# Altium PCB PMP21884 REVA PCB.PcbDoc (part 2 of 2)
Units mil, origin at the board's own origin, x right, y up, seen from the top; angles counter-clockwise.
Board outline 2378 x 1724 mil, 4 copper layers (Top Layer, Signal Layer 1, Signal Layer 2, Bottom Layer), stack 61.6 mil thick; 76 components, 35 nets, 187 pads, 142 vias.
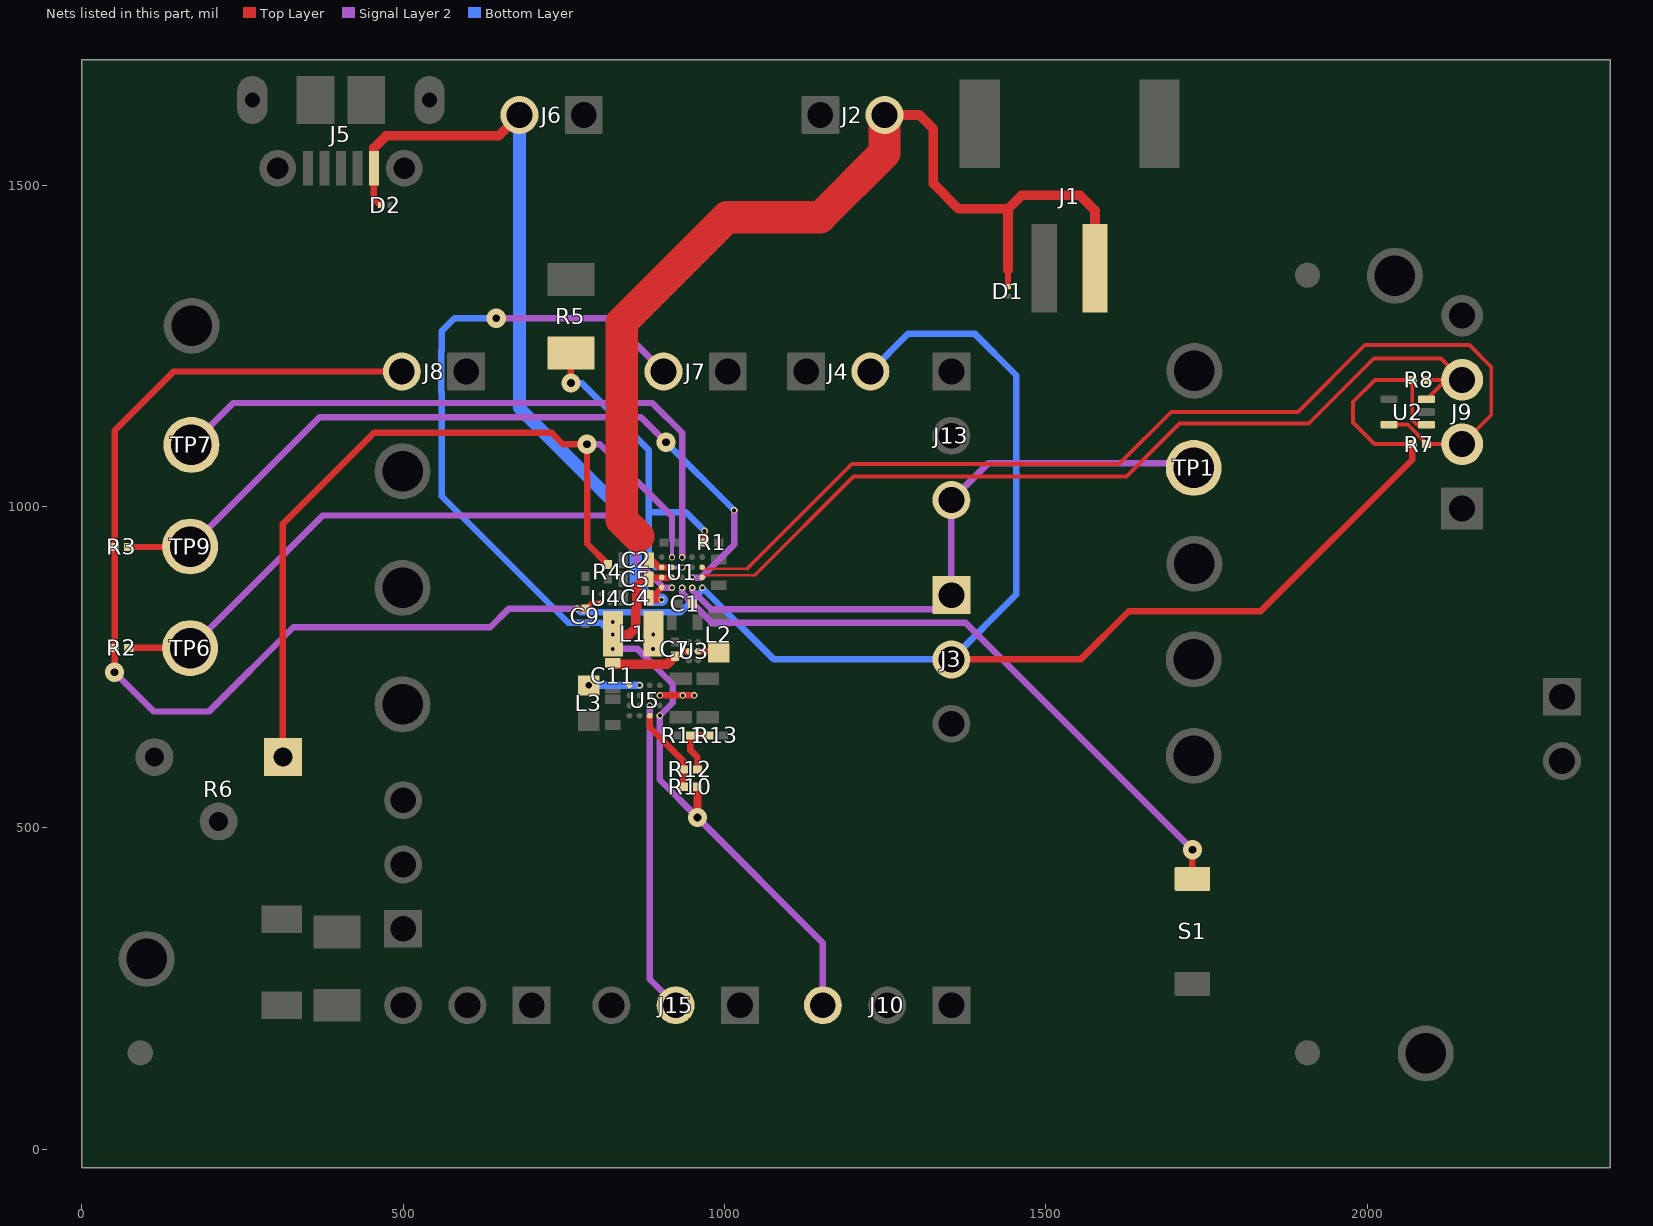
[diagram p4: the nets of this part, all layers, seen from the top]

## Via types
v1: diameter 30, hole 12, Top Layer to Bottom Layer, tented both sides, 95 vias
v2: diameter 10, hole 6, Top Layer to Bottom Layer, tented bottom, 30 vias
v3: diameter 10, hole 6, Top Layer to Bottom Layer, tented both sides, 16 vias
v4: diameter 20, hole 10, Top Layer to Bottom Layer, tented bottom, 1 vias

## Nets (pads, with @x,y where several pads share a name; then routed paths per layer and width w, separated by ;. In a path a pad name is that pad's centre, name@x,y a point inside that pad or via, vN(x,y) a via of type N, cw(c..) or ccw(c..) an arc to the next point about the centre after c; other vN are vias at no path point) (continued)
NetJ15_2: J15.2 U5.B3 | length 483
  Signal Layer 2 w10: v2(883.62,690.29) 883.62,264.38 J15.2@924,224
NetL1_2: L1.2 U5.A2 | length 53.6
  Top Layer w10: v2(899.37,706.04) v3(953,706) v3(953,706)
  other v2: 889,778 889.12,800.61
  other v3: 935,706.04
NetL2_1: L2.1 U3.B2 | length 32.8
  Top Layer w10: U3.B2@958.72,774.78 988.82,774.78 L2.1@990.72,772.89
NetL3_1: L3.1 U5.C1 | length 79
  Bottom Layer w12: v4(789,721.56) 789.23,721.78 v2(867.87,721.78)
NetR1_1: R1.1 R5.2 U1.C3 | length 556
  Top Layer w10: v1(761,1192) R5.2@761,1238.91 ; R1.1@968.95,944 R1.1@968.95,944 v3(969,962)
  Bottom Layer w6: 893.52,905.1 v2(934,905.1)
  Bottom Layer w10: v1(761,1192) 778,1192 882.21,1087.79 882.21,991 ; 893.52,905.1 882.21,916.41 882.21,991 ; v3(969,962) 940,991 882.21,991
NetR2_2: R2.2 TP6.1 U1.B1 | length 995.1
  Top Layer w10: R2.2@73.05,780 168.32,780 TP6.1@168.6,779.72
  Signal Layer 2 w10: TP6.1@168.6,779.72 374.88,986 823.2,986 862.82,946.38 862.82,916 905.22,873.61 v2(918.25,873.61)
NetR3_2: R3.2 TP9.1 U1.D2 | length 1225.3
  Top Layer w10: R3.2@73.05,937 167.88,937 TP9.1@168.6,937.72
  Signal Layer 2 w10: TP9.1@168.6,937.72 369.84,1138.96 870.04,1138.96 v1(909,1100) ; v2(949.75,889.36) 963.36,889.36 1015,941 v3(1015,994)
  Bottom Layer w10: v1(909,1100) v3(1015,994)
NetR4_1: R4.1 R6.1 U1.B4 | length 1345.9
  Top Layer w10: R6.1@313,610 313,973 455,1115 730.42,1115 748.42,1097 v1(786,1097) 786,1044 786.24,1044 786.24,942.04 R4.1@818.62,909.66
  Signal Layer 2 w6: v2(918.25,920.85) 918.25,948
  Signal Layer 2 w10: v1(786,1097) 806,1097 918.25,984.75 918.25,948
NetR10_1: R10.1 R12.2 U5.B4 | length 132.2
  Top Layer w10: U5.B4@883.62,674.54 883.62,656.38 935.95,604.05 R12.2@935.95,591 R10.1@935.95,564
NetR11_1: R11.1 R12.1 R13.2 | length 87
  Top Layer w10: R12.1@957.64,591.36 R12.1@958,591 958,610 947,621 R11.1@947,644 R13.2@975.98,644
NetS1_2: S1.2 U1.C1 | length 1012.9
  Top Layer w10: S1.2@1728,420.69 v1(1728,466)
  Signal Layer 2 w10: v2(934,873.61) 934,865.51 980.51,819 1375,819 v1(1728,466)
NetTP7_1: TP7.1 U1.C4 | length 1003.5
  Signal Layer 2 w10: TP7.1@170.6,1095.72 235.88,1161 887.75,1161 934,1114.75 v2(934,920.85)
PMID: C5.1 C7.1 C11.1 J7.2 J10.3 L1.1 R10.2 U1.A2 U1.B2 U3.B1 U5.A4 U5.D1 | length 2067.8
  Top Layer w10: C5.1@882.21,886.76 884.81,889.36 U1.B2@918.25,889.36 ; C7.1@923,766.98 927.07,766.98 934.87,774.78 U3.B1@944.94,774.78
  Top Layer w12: v1(958,516) R10.2@958,564
  Top Layer w15: C11.1@825.99,756.92 828.41,754.5 910.52,754.5 C7.1@923,766.98 ; v2(826.12,800.61) 851.42,800.61 861.87,811.05 861.87,838.83 ; 862.7,842.65 863.21,843.16 ; 863.21,842.15 863.21,843.16 ; C5.1@882.21,886.76 875.45,886.76 863.21,874.52 863.21,843.16
  Signal Layer 2 w10: v1(645,1293) 822,1293 J7.2@905,1210 ; v2(826.12,778.36) 864.64,778.36 919.37,723.63 919.37,694.54 v2(899.37,674.54) 899.37,574.63 v1(958,516) 1153,321 J10.3@1153,224
  Bottom Layer w10: v1(645,1293) 580,1293 560,1273 560,1242.57 559.47,1242.04 559.47,1177.96 560,1177.43 560,1016 757,819 807.73,819 v2(826.12,800.61)
  other v2: 826.12,820.36
SCL: J9.2 R7.1 U1.E3 U2.5 | length 1653.5
  Top Layer w4: U1.E3@965.5,903.11 1035.11,903.11
  Top Layer w6: U1.E3@965.5,903.11 U1.E3@965.5,905.1 ; 1035.11,903.11 1198,1066 1614,1066 1695,1147 1892,1147 1996,1251 2159,1251 2193,1217 2193,1142.41 J9.2@2147.59,1097 R7.1@2092,1097 2092,1098.24 2062.92,1127.31 U2.5@2033.84,1127.31
SDA: J9.3 R8.2 U1.E2 U2.3 | length 1435.3
  Top Layer w4: U1.E2@965.5,889.36 969.25,893.11 1047.11,893.11
  Top Layer w6: 1047.11,893.11 1200.53,1046.53 1625.53,1046.53 1708,1129 1909,1129 2010,1230 2114.59,1230 J9.3@2147.59,1197 J9.3@2122.43,1197 ; R8.2@2092,1197 J9.3@2122.43,1197 ; U2.3@2092.11,1166.68 J9.3@2122.43,1197
VBAT: C2.1 D1.2 J1.1 J2.2 U1.A3 U1.B3 | length 1627.7
  Top Layer w10: C2.1@882.43,916.19 887.37,916.19 898.45,905.1 U1.B3@918.25,905.1 ; D1.2@1441,1342.16 1441,1368
  Top Layer w15: J2.2@1249,1609 1303,1609 1325,1587 1325,1502.25 1364.25,1463 1441,1463 ; 1441,1368 1441,1463 ; J1.1@1576.37,1370.86 1576.37,1460.63 1553,1484 1462,1484 1441,1463
  Top Layer w50: 866,953.14 840.2,978.93 840.2,1286.22 1003.98,1450 1149,1450 1249,1550 J2.2@1249,1609
VDD: C1.1 J3.1 J13.3 TP1.1 U1.D1 | length 980.2
  Signal Layer 2 w10: v2(949.75,873.61) 949.75,869.56 979.31,840 1331,840 J3.1@1353,862 J13.3@1353,1010 1410,1067 1723,1067 TP1.1@1730,1060
VIN: C4.1 D2.2 J5.1 J6.2 U1.A1 | length 1239.7
  Top Layer w10: J5.1@454.39,1526.3 454.39,1479.04 D2.2@464.42,1469 ; C4.1@882.21,857.76 C4.1@886.66,857.76 ; v3(902,855) 889.42,855 C4.1@886.66,857.76 ; U1.A1@902.51,873.61 C4.1@886.66,857.76
  Top Layer w15: J5.1@454.39,1526.3 454.39,1557.98 473,1576.6 648.6,1576.6 J6.2@681,1609
  Bottom Layer w20: J6.2@681,1609 681,1152.75 861.87,971.88 861.87,878.1 884.97,855 v3(902,855)
VIO: C9.1 J3.2 J4.2 J8.2 R2.1 R3.1 R7.2 R8.1 U1.E1 U2.1 U4.A1 | length 4326.5
  Top Layer w6: R7.2@2069.95,1097 2011.41,1097 1978,1130.41 1978,1163 2012,1197 R8.1@2069.95,1197 2069.95,1134.43 2077.07,1127.31 U2.1@2092.11,1127.31
  Top Layer w8: C9.1@783.62,840.28 783.95,840.61 793.45,850.11 U4.A1@808.11,850.11
  Top Layer w10: v1(51,742) R2.1@51,780 R3.1@51,937 51,1118 143,1210 J8.2@498,1210 ; v3(771,840.61) C9.1@783.95,840.61 ; J3.2@1353,762 1553.82,762 1628.82,837 1834,837 2069.95,1072.95 R7.2@2069.95,1097
  Signal Layer 2 w10: v1(51,742) 112,681 198,681 329,812 635.39,812 664,840.61 v3(771,840.61)
  Bottom Layer w10: v3(771,840.61) 776,835.61 931.55,835.61 965.5,869.56 v2(965.5,873.61) 1077.11,762 J3.2@1353,762 1454,863 1454,1204 1389,1269 1286,1269 J4.2@1227,1210
pads on no net: FID1.1 FID2.1 FID3.1 J1.M1 J1.M2 J5.2 J5.3 J5.4 J9.4 U2.2

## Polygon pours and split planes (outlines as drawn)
1V2 on Top Layer "TOP_LAYER_1V2_P012" (solid, remove dead copper, pour order 12): 813,859 768,859 768,880 801,880 813.01,867.99
VDD on Top Layer "TOP_LAYER_VDD_P058" (solid, remove dead copper, pour order 58): 950,876.61 942,868.61 942,837.61 943,836.61 956,836.61 956,870.61
GND on Top Layer "TOP_LAYER_GND_P028" (solid, remove dead copper, pour order 28): 0,-29 2378,-29 2378,1695 0,1695
GND on Signal Layer 2 "SIGNAL_LAYER_2_GND_P030" (solid, remove dead copper, pour order 30): 0,-29 2378,-29 2378,1695 0,1695
GND on Signal Layer 1 "SIGNAL_LAYER_1_GND_P032" (solid, remove dead copper, pour order 32): 0,-29 2378,-29 2378,1695 0,1695
GND on Bottom Layer "BOTTOM_LAYER_GND_P034" (solid, remove dead copper, pour order 34): 0,-29 2378,-29 2378,1710 0,1710

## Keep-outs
Keep-Out Layer:
  text ".Layer_Name" at 537,-918.49 h60

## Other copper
Top Layer:
  region: 945,780
  region net PMID: 810.62,835.61 810.62,791.61 852.61,791.61 869.62,808.62 869.62,842.61 854.62,842.61 847.62,835.61
  region net PMID: 848,806 856,798 856,719 852,719 840,731 814.42,731 810.42,735 810.42,806
  region net 1V8_C: 855,694 846,694 834,682 772,682 772,651 774,649 838,649 840,651 840,676 855,691
  region net GND: 814,724 814,692 838,692 838,695 844,701 854,701 857,704 857,709 855,711 848,711 835,724
  region net VIN: 906,877 899,877 892,870 875,870 875,846 906,846 911,851 911,859 905.97,864.03
  region net 12V: 915,663 915,678 908,685 898,685 898,695 923,695 923,663
  region net 1V8_B: 958.32,784.31 958.32,803.04 952.19,809.18 952.19,829.19 976.18,853.18 1041.19,853.18 1053.19,841.18 1053.19,816.04 1040.19,803.04 977.06,803.04
  region net VBAT: 906,901 906,904 900,910 891.75,910 890,911.75 890,957 880,967 830,967 857,940 857,911 865,903 892,903 894,901
  region net GND: 944.94,785.41
  text ".Layer_Name" at 537,-918.49 h60
Signal Layer 2:
  region: 863.75,858.7
Bottom Layer:
  region net NetL1_2: 898,711 904,711 911,718 911,731 875,767 875,807 904,807 904,789 963,730 963,698 905,698 898,705
  text ".Layer_Name" at 537,-918.49 h60

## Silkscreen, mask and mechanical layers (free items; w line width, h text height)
Top Overlay:
  region: 1003.6,955.81
  region: 910.44,833.78
  lines w10: 249,926 324,926 ; 255,769 305,769 ; 574,1323 624,1323 ; 1103,1319 1153,1319 ; 1798,396 1848,396
  text "'.PRJ_Number'.PCB_Rev" at 1756,1549 h108.27
  text "VIN" at 632,1508 h30
  text "GND" at 751,1508 h30
  text "GND" at 1094,1508 h30
  text "VBAT" at 1205,1508 h30
  text "GND" at 2126,1355 h30
  text "GND" at 252,1284 h30
  text "VIO" at 458,1279 h30
  text "CE" at 574,1279 h30
  text "PMID" at 820,1277 h30
  text "VINLS" at 944,1277 h30
  text "LP" at 1105,1277 h30
  text "VIO" at 1201,1277 h30
  text "OFF" at 1416,1198 h30
  text "1V8_A" at 1812,1171 h30
  text "1V8_B" at 1416,1100 h30
  text "ADCIN" at 252,1062 h30
  text "1V2" at 583,1026 h30
  text "VDD" at 1812,1007 h30
  text "ON" at 1416,994 h30
  text "INT" at 250,883 h30
  text "1V8_B" at 1812,876 h30
  text "1V8_C" at 578,849 h30
  text "VDD" at 1416,836 h30
  text "VIO" at 1416,734 h30
  text "PG" at 255,728 h30
  text "12V" at 1812,718.84 h30
  text "GND" at 2145.96,682 h30
  text "1V8_D" at 579,659 h30
  text "EXT_VIO" at 1416,639 h30
  text "EXT_VIO" at 2031,583 h30
  text "GND" at 1809,560 h30
  text "ON" at 565,532 h30
  text "1V2" at 565,434 h30
  text "MR" at 1799,353 h30
  text "OFF" at 565,329 h30
  text "GND" at 180,303 h30
  text "GND" at 2174,146 h30
  text "ON" at 517,105.99 h30 r90
  text "ON" at 840,105.99 h30 r90
  text "ON" at 1169,105.99 h30 r90
  text "12V" at 938,81 h30 r90
  text "OFF" at 720,76 h30 r90
  text "OFF" at 1043,76 h30 r90
  text "OFF" at 1372,76 h30 r90
  text "1V8_C" at 615,21.02 h30 r90
  text "1V8_D" at 1267,21.02 h30 r90
  text ".Layer_Name" at 537,-918.49 h60
Bottom Overlay:
  text ".Layer_Name" at 537,-918.49 h60
Top Paste:
  text ".Layer_Name" at 537,-918.49 h60
Bottom Paste:
  text ".Layer_Name" at 537,-918.49 h60
Top Solder:
  text ".Layer_Name" at 537,-918.49 h60
  text ".Layer_Name" at 537,-918.49 h60
Bottom Solder:
  text ".Layer_Name" at 537,-918.49 h60
Drill Guide:
  text ".Layer_Name" at 537,-918.49 h60
M1 Board Outline:
  the board outline again, w10
  text ".Layer_Name" at 537,-918.49 h60
M2 Board Dimensions:
  rectangle: -40,-335 85,-210
  rectangle: 85,-460 460,-335
  lines w7: -40,-335 960,-335 ; 85,-460 85,-210 ; 210,-460 210,-210 ; 460,-460 460,-210 ; 710,-460 710,-210 ; -40,-460 960,-460 960,-210 -40,-210 -40,-460
  text ".Layer_Name" at 537,-918.49 h60
M3 3D STEP Top:
  text ".Layer_Name" at 537,-918.49 h60
M4 3D STEP Bottom:
  text ".Layer_Name" at 537,-918.49 h60
M5 Assembly Top:
  lines w10: -332,-990.17 6268,-990.17 ; -332,-786.83 6270,-786.83 ; -332,-583.5 -332,-1193.5 3673,-1193.5 6270,-1193.5 6270,-583.5 -331.5,-583.5 -331.5,-1193.5 1244,-1193.5 ; 2133,-1193.5 2133,-583.5 ; 3400,-786.83 3400,-583.5 ; 4240,-786.83 4240,-583.5 ; 4862,-1200 4862,-997.17
  text "COMPONENTS MARKED 'DNP' SHOULD NOT BE POPULATED." at 1113.5,-378.5 h60
  text "ASSEMBLY VARIANT:" at 1113,-494 h60
  text ".VariantName" at 2149,-494 h60
  text "PCB VIEWED FROM TOP SIDE" at -268.5,-715.67 h60
  text "BOARD #:" at 2208,-715.67 h60
  text ".PRJ_Number" at 2753.5,-715.67 h60
  text "REV:" at 3598,-715.67 h60
  text ".PCB_Rev" at 3889.5,-715.67 h60
  text "SVN REV:" at 4436,-715.67 h60
  text ".VersionControl_RevNumber" at 4942,-715.67 h60
  text "TID #:" at 2208,-919 h60
  text ".TID" at 2753.5,-919 h60
  text "PLOT NAME =" at -268.5,-1124.34 h60
  text ".plot_File_Name" at 537,-1124.34 h60
  text "GENERATED    :" at 2210,-1124.34 h60
  text ".Print_Date" at 3079.5,-1124.34 h60
  text ".Print_Time" at 3808.5,-1124.34 h60
  text "TEXAS INSTRUMENTS" at 5073,-1124.34 h60
M6 Assembly Bottom:
  lines w10: -332.5,-787.33 6269.5,-787.33 ; -330.5,-990.67 6269.5,-990.67 ; 1075.5,-1200.5 1075.5,-997.67 ; 1697.5,-787.33 1697.5,-584 ; 2537.5,-787.33 2537.5,-584 ; 3804.5,-1194 3804.5,-584 ; 4693.5,-1194 6269,-1194 6269,-584 -332.5,-584 -332.5,-1194 2264.5,-1194 6269.5,-1194 6269.5,-584
  text "COMPONENTS MARKED 'DNP' SHOULD NOT BE POPULATED." at 6062,-378 h60
  text ".VariantName" at 5018,-494 h60
  text "ASSEMBLY VARIANT:" at 6057,-494 h60
  text ".VersionControl_RevNumber" at 995.5,-716.17 h60
  text "SVN REV:" at 1501.5,-716.17 h60
  text ".PCB_Rev" at 2048,-716.17 h60
  text "REV:" at 2339.5,-716.17 h60
  text ".PRJ_Number" at 3184,-716.17 h60
  text "BOARD #:" at 3729.5,-716.17 h60
  text "PCB VIEWED FROM BOTTOM SIDE" at 6206,-716.17 h60
  text ".TID" at 3184,-919.5 h60
  text "TID #:" at 3729.5,-919.5 h60
  text "TEXAS INSTRUMENTS" at 864.5,-1124.84 h60
  text ".Print_Time" at 2129,-1124.84 h60
  text ".Print_Date" at 2858,-1124.84 h60
  text "GENERATED    :" at 3727.5,-1124.84 h60
  text ".plot_File_Name" at 5400.5,-1124.84 h60
  text "PLOT NAME =" at 6206,-1124.84 h60
M9 Title Sheet:
  drawing of 57 lines, arcs and shapes, not listed
  text "1" at 699.84,7976.5 h70
  text "2" at 3195.5,7976.5 h70
  text "3" at 5684.84,7976.5 h70
  text "4" at 8191.51,7976.5 h70
  text "5" at 10690.5,7976.5 h70
  text "6" at 13195.5,7976.5 h70
  text "A" at -456.5,6833.5 h70
  text "A" at 14343.5,6833.5 h70
  text "B" at -456.5,4453.5 h70
  text "B" at 14343.5,4453.5 h70
  text "C" at -456.5,2078.5 h70
  text "C" at 14343.5,2078.5 h70
  text "PROJECT TITLE:" at 11303.5,217.5 h45
  text ".PRJ_Title" at 11353.5,84.17 h70
  text "DESIGNED FOR:" at 11303.5,-83.5 h45
  text ".PRJ_Customer" at 11353.5,-223.5 h70
  text "D" at -456.5,-291.5 h70
  text "D" at 14343.5,-291.5 h70
  text "FILE NAME:" at 11303.5,-383.5 h45
  text ".PCB_File_Name_No_Path" at 11353.5,-503.5 h70
  text "Texas Instruments (TI) and/or its licensors do not warrant the accuracy or completeness of this specification" at 6334,-665.34 h45
  text "ENGINEER:" at 11303.5,-673.5 h45
  text "LAYOUT BY:" at 12808.5,-673.5 h45
  text "or any information contained therein. TI and/or its licensors do not warrant that this design will meet" at 6289.01,-778 h45
  text ".PRJ_Engineer" at 11353.5,-828.49 h70
  text ".PCB_Layout" at 12859,-828.49 h70
  text "the specifications, will be suitable for your application or fit for any particular purpose, or will operate in" at 6289.01,-890.67 h45
  text ".Layer_Name" at 537,-918.49 h60
  text "ALTIUM DESIGNER VERSION:" at 12808.5,-983.5 h45
  text "an implementation. TI and/or its licensors do not warrant that the design is production worthy. You should" at 6289.01,-1003.33 h45
  text "completely validate and test your design implementation to confirm the system functionality for your application." at 6334,-1116 h45
  text ".print_Scale" at 11353.5,-1116.83 h70
  text ".Application_BuildNumber" at 12859,-1116.83 h70
  text "1" at 699.84,-1323.5 h70
  text "2" at 3195.5,-1323.5 h70
  text "3" at 5684.84,-1323.5 h70
  text "4" at 8191.51,-1323.5 h70
  text "5" at 10690.5,-1323.5 h70
  text "6" at 13195.5,-1323.5 h70
M10 Fab Notes:
  drawing of 189 lines, arcs and shapes, not listed
  text "DESIGN INFORMATION" at 12342.02,6296.17 h60
  text "MIN. TRACK WIDTH:" at 11697.46,6164.05 h60
  text "8" at 12793.7,6164.05 h60
  text "MIL" at 12948.46,6164.05 h60
  text "MIN. CLEARANCE:" at 11697.46,6039.92 h60
  text "0.2" at 12733.7,6039.93 h60
  text "mm" at 12948.46,6039.92 h60
  text "MIN. VIA PAD SIZE:" at 11697.46,5915.8 h60
  text "24" at 12763.71,5915.8 h60
  text "MIL" at 12948.46,5915.8 h60
  text "0.05mm (2MIL)" at 12392.46,5785.9 h60
  text "MINIMUM ANNULAR RING" at 11368.23,5777.67 h60
  text "EXTERNAL" at 13100.46,5777.67 h60
  text "PER" at 11568.23,5667.55 h60
  text "IPC-D-275 CLASS 2 LEVEL C" at 11788.23,5667.54 h60
  text "MIL, HOLES" at 13276.46,5567.07 h60
  text "+/-" at 12884,5558.48 h60
  text "+/-" at 13738,5558.48 h60
  text "REGISTRATION TOLERANCES:" at 11368.23,5557.42 h60
  text "METAL" at 12568,5557.42 h60
  text "5" at 13144.2,5557.42 h60
  text "3" at 13977.2,5557.42 h60
  text "MIL" at 14093.46,5557.42 h60
  text "HOLE SIZE TOLERANCE (UNLESS OTHERWISE SPECIFIED):" at 11368.23,5459.1 h60
  text "+/-" at 13738,5456.23 h60
  text "3" at 13977.2,5455.17 h60
  text "MIL" at 14093.46,5455.17 h60
  text "MATERIAL:" at 11293.46,5317.52 h60
  text "FR-4 High Tg" at 12279.9,5189 h60
  text "X" at 12135.46,5181.01 h60
  text "FR-408" at 11714.46,5176.49 h60
  text "OTHER" at 13202.46,5176.49 h60
  text "62 MIL (1.6mm) +/-10%" at 12034.56,5033.46 h60
  text "X" at 11914.46,5031.01 h60
  text "THICKNESS:" at 11368.23,5025.24 h60
  text "OTHER" at 13319.46,5025.24 h60
  text "TOLERANCE:" at 11368.23,4886.92 h60
  text "X" at 12216.46,4886.92 h60
  text "ANSI IPC-6012 TYPE 3 CLASS 2" at 12394.48,4886.92 h60
  text "OTHER +/-" at 12394.46,4742.73 h60
  text "BOW & TWIST:" at 11368.23,4597.54 h60
  text "X" at 12216.46,4597.54 h60
  text "ANSI IPC-6012 TYPE 3 CLASS 2" at 12394.48,4597.54 h60
  text "OTHER +/-" at 12394.46,4450.85 h60
  text "DRILLING:" at 11293.46,4320.23 h60
  text "NC_DRILL FILES" at 13054.46,4215.04 h60
  text "REFERENCE:" at 11368.23,4211.1 h60
  text "X" at 12025.46,4211.01 h60
  text "AS SHOWN" at 12203.46,4211.1 h60
  text "X" at 12926.46,4211.1 h60
  text "OTHER" at 13352.46,4068.85 h60
  text "PTH COPPER THICKNESS:" at 11367.91,4065.32 h60
  text "X" at 12507.14,4065.32 h60
  text "20-30 um" at 12635.14,4065.32 h60
  text "BOARD FINISH:" at 11293.46,3917.73 h60
  text "SILKSCREEN:" at 11448.68,3807.6 h60
  text "X" at 12406.46,3807.6 h60
  text "TOP" at 12523.46,3807.6 h60
  text "X" at 12916.46,3807.6 h60
  text "BOTTOM" at 13034.46,3807.6 h60
  text "SILKSCREEN COLOR:" at 11448.68,3652.41 h60
  text "X" at 12405.46,3652.41 h60
  text "WHITE" at 12523.46,3652.41 h60
  text "OTHER" at 13034.46,3652.41 h60
  text "X" at 12536.46,3508.96 h60
  text "GREEN" at 12654.46,3508.96 h60
  text "OTHER" at 13272.46,3508.96 h60
  text "SOLDER RESIST COLOR:" at 11448.68,3502.1 h60
  text "X" at 12536.46,3354.71 h60
  text "MATTE" at 12654.46,3354.71 h60
  text "SEMI-GLOSS" at 13272,3354.07 h60
  text "IMMERSION GOLD (ENIG)" at 12354.46,3181.94 h60
  text "ENEPIG" at 13692,3174.72 h60
  text "SURFACE FINISH:" at 11293.46,3173.72 h60
  text "X" at 12176.46,3173.72 h60
  text "IMM. TIN/SILVER OR EQUIV" at 11623,3036.4 h60
  text "OTHER" at 13054.46,3032.47 h60
  text "ARRAY/PANEL:" at 11293.46,2877.09 h60
  text "CUT AND TRIM PER M1 BOARD OUTLINE" at 12354.46,2868.87 h60
  text "N.C. ROUTE" at 12354.46,2732.9 h60
  text "X" at 13042.46,2732.9 h60
  text "V. SCORE" at 13220.46,2732.9 h60
  text "CERTIFICATION:" at 11293.46,2603.77 h60
  text "MATERIALS AND WORKMANSHIP FOR ALL PCBS" at 12018.46,2603.77 h60
  text "TO MEET OR EXCEED THE REQUIREMENTS OF:" at 12018.46,2509.71 h60
  text "X" at 11655.97,2381.08 h60
  text "ANSI IPC-A-600F CLASS ->" at 11783.96,2381.08 h60
  text "X" at 13431.97,2381.08 h60
  text "2" at 13541.96,2381.08 h60
  text "1" at 13226.96,2379.58 h60
  text "3" at 13895.96,2379.58 h60
  text "X" at 12467.97,2233.39 h60
  text "RoHS" at 12595.96,2233.39 h60
  text "OTHER" at 13240.36,2233.39 h60
  text "PER ORDER" at 13637.42,2233.39 h60
  text "ALL BOARDS MUST MEET OR EXCEED UL94-V0 REQUIREMENTS." at 11321,2079.57 h60
  text "PCB MUST BEAR THE UL94V-0 UL REGISTERED MATERIAL ID NUMBER" at 11321,1963.5 h60
  text "ADDITIONAL REQUIREMENTS:" at 11293.46,1794.08 h60
  text "MICROSECTION:" at 11368.23,1686.95 h60
  text "YES" at 12273.96,1686.95 h60
  text "REQUIRED" at 13135.46,1542.62 h60
  text "BARE BOARD ELEC. TEST:" at 11368.23,1539.76 h60
  text "NONE" at 12673.96,1539.76 h60
  text "X" at 13017.46,1539.76 h60
  text "PER ORDER" at 13727.46,1539.76 h60
  text "XX MIL VIAS REQUIRE NON-CONDUCTIVE FILL AND PLANARIZE" at 11536.38,1334.82 h59
  text "XX MIL VIAS REQUIRE CONDUCTIVE FILL AND PLANARIZE" at 11544.38,1230.84 h60
  text "OUTER XX MIL TRACES REQUIRE 50 OHM SINGLE-ENDED IMPEDANCE" at 11543.39,1067.46 h58
  text "LAYER 2 & 3 (INNER LAYERS) XX MIL WIDE, XX MIL SPACE / TRACES REQUIRE 100 OHM DIFFERENTIAL IMPEDANCE" at 11535.39,831.74 h60
  text ".Layer_Name" at 537,-918.49 h60
M11 Gerber Information:
  lines w10: -332,-990.17 6268,-990.17 ; -332,-786.83 6270,-786.83 ; -332,-583.5 -332,-1193.5 3673,-1193.5 6270,-1193.5 6270,-583.5 -331.5,-583.5 -331.5,-1193.5 1244,-1193.5 ; 2133,-1193.5 2133,-583.5 ; 3400,-786.83 3400,-583.5 ; 4240,-786.83 4240,-583.5 ; 4862,-1200 4862,-997.17
  text "ALL ARTWORK VIEWED FROM TOP SIDE" at -268.5,-715.67 h60
  text "BOARD #:" at 2208,-715.67 h60
  text ".PRJ_Number" at 2753.5,-715.67 h60
  text "REV:" at 3598,-715.67 h60
  text ".PCB_Rev" at 3889.5,-715.67 h60
  text "SVN REV:" at 4436,-715.67 h60
  text ".VersionControl_RevNumber" at 4942,-715.67 h60
  text "LAYER NAME =" at -268.5,-918.49 h60
  text "TID #:" at 2208,-919 h60
  text ".TID" at 2753.5,-919 h60
  text "PLOT NAME =" at -268.5,-1124.34 h60
  text ".plot_File_Name" at 537,-1124.34 h60
  text "GENERATED    :" at 2210,-1124.34 h60
  text ".Print_Date" at 3079.5,-1124.34 h60
  text ".Print_Time" at 3808.5,-1124.34 h60
  text "TEXAS INSTRUMENTS" at 5073,-1124.34 h60
M12 Stackup:
  drawing of 295 lines, arcs and shapes, not listed
  text "Layer" at 9771.59,6959.94 h60
  text "Name" at 10181.51,6959.94 h60
  text "Material" at 11121.25,6959.94 h60
  text "Thickness" at 11981.02,6959.94 h60
  text "Constant" at 12630.85,6959.94 h60
  text "Board Layer Stack" at 13200.71,6959.94 h60
  text "1" at 9771.59,6839.94 h60
  text "Top Overlay" at 10181.51,6839.94 h60
  text "2" at 9771.59,6719.94 h60
  text "Top Solder" at 10181.51,6719.94 h60
  text "Solder Resist" at 11121.25,6719.94 h60
  text "0.40mil" at 11981.02,6719.94 h60
  text "3.5" at 12630.85,6719.94 h60
  text "3" at 9771.59,6599.94 h60
  text "Top Layer" at 10181.51,6599.94 h60
  text "Copper" at 11121.25,6599.94 h60
  text "1.40mil" at 11981.02,6599.94 h60
  text "4" at 9771.59,6479.94 h60
  text "Dielectric 1" at 10181.51,6479.94 h60
  text "FR-4" at 11121.25,6479.94 h60
  text "8.00mil" at 11981.02,6479.94 h60
  text "4.2" at 12630.85,6479.94 h60
  text "5" at 9771.59,6359.94 h60
  text "Signal Layer 1" at 10181.51,6359.94 h60
  text "Copper" at 11121.25,6359.94 h60
  text "1.40mil" at 11981.02,6359.94 h60
  text "6" at 9771.59,6239.94 h60
  text "Dielectric 2" at 10181.51,6239.94 h60
  text "FR-4" at 11121.25,6239.94 h60
  text "40.00mil" at 11981.02,6239.94 h60
  text "4.2" at 12630.85,6239.94 h60
  text "7" at 9771.59,6119.94 h60
  text "Signal Layer 2" at 10181.51,6119.94 h60
  text "Copper" at 11121.25,6119.94 h60
  text "1.40mil" at 11981.02,6119.94 h60
  text "8" at 9771.59,5999.94 h60
  text "Dielectric 3" at 10181.51,5999.94 h60
  text "FR-4" at 11121.25,5999.94 h60
  text "8.00mil" at 11981.02,5999.94 h60
  text "4.2" at 12630.85,5999.94 h60
  text "9" at 9771.59,5879.94 h60
  text "Bottom Layer" at 10181.51,5879.94 h60
  text "Copper" at 11121.25,5879.94 h60
  text "1.40mil" at 11981.02,5879.94 h60
  text "10" at 9771.59,5759.94 h60
  text "Bottom Solder" at 10181.51,5759.94 h60
  text "Solder Resist" at 11121.25,5759.94 h60
  text "0.40mil" at 11981.02,5759.94 h60
  text "3.5" at 12630.85,5759.94 h60
  text "11" at 9771.59,5639.94 h60
  text "Bottom Overlay" at 10181.51,5639.94 h60
  text ".Layer_Name" at 537,-918.49 h60
M13 Component Bodies Top:
  text ".Layer_Name" at 537,-918.49 h60
M14 Component Bodies Bottom:
  text ".Layer_Name" at 537,-918.49 h60
M15 Courtyards Top:
  text ".Layer_Name" at 537,-918.49 h60
M16 Courtyards Bottom:
  text ".Layer_Name" at 537,-918.49 h60
Drill Drawing:
  circle w10: c5323.63,2888.56 r27.59
  lines w10: 5296.04,2626.41 5309.83,2626.41 5323.63,2612.61 5337.43,2626.41 5351.23,2626.41 5337.43,2640.21 5351.23,2654.01 5337.43,2654.01 5323.63,2667.8 5309.83,2654.01 5296.04,2654.01 5309.83,2640.21 5296.04,2626.41 ; 5296.04,2764.39 5323.63,2736.79 5351.23,2764.39 5323.63,2791.98 5296.04,2764.39 ; 5296.04,3040.33 5351.23,3040.33 5323.63,2985.14 5296.04,3040.33 ; 5296.04,3109.32 5323.63,3123.12 5351.23,3109.32 5337.43,3136.91 5351.23,3164.51 5323.63,3150.71 5296.04,3164.51 5309.83,3136.91 5296.04,3109.32 ; 5296.04,3233.49 5351.23,3233.49 5351.23,3288.68 5296.04,3288.68 5296.04,3233.49 ; 5296.04,3357.67 5296.04,3371.47 5309.83,3385.27 5296.04,3399.06 5296.04,3412.86 5309.83,3412.86 5323.63,3399.06 5337.43,3412.86 5351.23,3412.86 5351.23,3399.06 5337.43,3385.27 5351.23,3371.47 5351.23,3357.67 5337.43,3357.67 5323.63,3371.47 5309.83,3357.67 5296.04,3357.67 ; 5296.04,3481.85 5351.23,3481.85 5351.23,3537.04 5296.04,3537.04 5296.04,3481.85 ; 5296.04,3619.82 5309.83,3619.82 5309.83,3606.02 5337.43,3606.02 5337.43,3619.82 5351.23,3619.82 5351.23,3647.41 5337.43,3647.41 5337.43,3661.21 5309.83,3661.21 5309.83,3647.41 5296.04,3647.41 5296.04,3619.82 ; 5307.07,3492.88 5340.19,3492.88 5340.19,3526 5307.07,3526 5307.07,3492.88
  lines w12: 5246,2575.36 8476.52,2575.36 ; 5246,3692.95 8476.52,3692.95 ; 5583.86,2451.19 5583.86,3817.12 ; 5915.86,2451.19 5915.86,3817.12 ; 6552.42,2451.19 6552.42,3817.12 ; 6811.53,2451.19 6811.53,3817.12 ; 7186.68,2451.19 7186.68,3817.12 ; 7910.06,2451.19 7910.06,3817.12 ; 5246,2451.19 8476.52,2451.19 8476.52,3817.12 5246,3817.12 5246,2451.19
  text "Symbol" at 5320.51,3730.2 h72
  text "Quantity" at 5621.11,3730.2 h72
  text "Finished Hole Size" at 5953.12,3730.2 h72
  text "Plated" at 6589.67,3730.2 h72
  text "Hole Type" at 6848.78,3730.2 h72
  text "Drill Layer Pair" at 7223.93,3730.2 h72
  text "Hole Tolerance" at 7947.32,3730.2 h72
  text "46" at 5621.11,3606.02 h60
  text "6.00mil (0.152mm)" at 5953.12,3606.02 h60
  text "PTH" at 6589.67,3606.02 h60
  text "Round" at 6848.78,3606.02 h60
  text "Top Layer - Bottom Layer" at 7223.93,3606.02 h60
  text "1" at 5621.11,3481.85 h60
  text "10.00mil (0.254mm)" at 5953.12,3481.85 h60
  text "PTH" at 6589.67,3481.85 h60
  text "Round" at 6848.78,3481.85 h60
  text "Top Layer - Bottom Layer" at 7223.93,3481.85 h60
  text "95" at 5621.11,3357.67 h60
  text "12.00mil (0.305mm)" at 5953.12,3357.67 h60
  text "PTH" at 6589.67,3357.67 h60
  text "Round" at 6848.78,3357.67 h60
  text "Top Layer - Bottom Layer" at 7223.93,3357.67 h60
  text "3" at 5621.11,3233.49 h60
  text "29.53mil (0.750mm)" at 5953.12,3233.49 h60
  text "PTH" at 6589.67,3233.49 h60
  text "Round" at 6848.78,3233.49 h60
  text "Top Layer - Bottom Layer" at 7223.93,3233.49 h60
  text "2" at 5621.11,3109.32 h60
  text "33.47mil (0.850mm)" at 5953.12,3109.32 h60
  text "PTH" at 6589.67,3109.32 h60
  text "Round" at 6848.78,3109.32 h60
  text "Top Layer - Bottom Layer" at 7223.93,3109.32 h60
  text "30" at 5621.11,2985.14 h60
  text "40.00mil (1.016mm)" at 5953.12,2985.14 h60
  text "PTH" at 6589.67,2985.14 h60
  text "Round" at 6848.78,2985.14 h60
  text "Top Layer - Bottom Layer" at 7223.93,2985.14 h60
  text "4" at 5621.11,2860.97 h60
  text "40.16mil (1.020mm)" at 5953.12,2860.97 h60
  text "PTH" at 6589.67,2860.97 h60
  text "Round" at 6848.78,2860.97 h60
  text "Top Layer - Bottom Layer" at 7223.93,2860.97 h60
  text "15" at 5621.11,2736.79 h60
  text "63.00mil (1.600mm)" at 5953.12,2736.79 h60
  text "PTH" at 6589.67,2736.79 h60
  text "Round" at 6848.78,2736.79 h60
  text "Top Layer - Bottom Layer" at 7223.93,2736.79 h60
  text "2" at 5621.11,2612.61 h60
  text "23.62mil (0.600mm)" at 5953.12,2612.61 h60
  text "PTH" at 6589.67,2612.61 h60
  text "Slot" at 6848.78,2612.61 h60
  text "Top Layer - Bottom Layer" at 7223.93,2612.61 h60
  text "198 Total" at 5621.11,2488.44 h60
  text "Slot definitions :" at 5320.51,2401.52 h60
  text "Routed Path Length" at 5770.51,2401.52 h60
  text "= Calculated from tool start centre position to tool end centre position." at 6309.42,2401.52 h60
  text "Hole Length" at 5770.51,2351.85 h60
  text "= Routed Path Length + Tool Size = Slot length as defined in the PCB layout" at 6109.91,2351.85 h60
  text ".Layer_Name" at 537,-918.49 h60
Mechanical 17:
  text ".Layer_Name" at 537,-918.49 h60
Mechanical 18:
  text ".Layer_Name" at 537,-918.49 h60
Mechanical 19:
  text ".Layer_Name" at 537,-918.49 h60

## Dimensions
-40,-460 to 960,-460 on M2 Board Dimensions
-40,-60 to 0,1695 on M2 Board Dimensions
0,-29 to 2378,-29 on M2 Board Dimensions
